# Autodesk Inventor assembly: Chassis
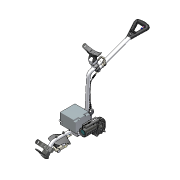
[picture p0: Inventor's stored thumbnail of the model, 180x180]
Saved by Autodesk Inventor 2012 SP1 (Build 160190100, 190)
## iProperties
Created: 2011-01
Part Number: Chassis
Document SubType Name: Assembly
Designer: eric
Mass: 5424.55 g
Surface Area: 15292.6 cm^2
Volume: 5424.55 cm^3
Density: 1 g/cm^3
Author: eric
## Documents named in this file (30)
- D:\Cours\Inventor salle SI\chariot_de_golf_2008\chariot_de_golf_trolem\Chassis.iam
- D:\Cours\Inventor salle SI\chariot_de_golf_2008\chariot_de_golf_trolem\59batterie_Defaut.ipt
- D:\Cours\Inventor salle SI\chariot_de_golf_2008\chariot_de_golf_trolem\montage1chassis_Defaut.iam
- D:\Cours\Inventor salle SI\chariot_de_golf_2008\chariot_de_golf_trolem\40Enjoliveur_M8_Defaut.ipt
- D:\Cours\Inventor salle SI\chariot_de_golf_2008\chariot_de_golf_trolem\5.1Vis CBLX M8-55.ipt
- D:\Cours\Inventor salle SI\chariot_de_golf_2008\chariot_de_golf_trolem\5.1cache-ecrouM10_Defaut.ipt
- D:\Cours\Inventor salle SI\chariot_de_golf_2008\chariot_de_golf_trolem\montage2timon_Defaut.iam
- D:\Cours\Inventor salle SI\chariot_de_golf_2008\chariot_de_golf_trolem\montage4tube_alu_Defaut.iam
- D:\Cours\Inventor salle SI\chariot_de_golf_2008\chariot_de_golf_trolem\montage_6cable_Defaut.iam
- D:\Cours\Inventor salle SI\chariot_de_golf_2008\chariot_de_golf_trolem\44Rondelle_M8_Defaut.ipt
- D:\Cours\Inventor salle SI\chariot_de_golf_2008\chariot_de_golf_trolem\33vis M6_60.ipt
- D:\Cours\Inventor salle SI\chariot_de_golf_2008\chariot_de_golf_trolem\32vis M8_60.ipt
- D:\Cours\Inventor salle SI\chariot_de_golf_2008\chariot_de_golf_trolem\39Ecrou H_ FR_ M8.ipt
- D:\Cours\Inventor salle SI\chariot_de_golf_2008\chariot_de_golf_trolem\35Vis_CBLZ_M6_55.ipt
- D:\Cours\Inventor salle SI\chariot_de_golf_2008\chariot_de_golf_trolem\36Ecrou H_ FR_ M6.ipt
- D:\Cours\Inventor salle SI\chariot_de_golf_2008\chariot_de_golf_trolem\30Ressort_e1.5_Defaut.ipt
- D:\Cours\Inventor salle SI\chariot_de_golf_2008\chariot_de_golf_trolem\5.1 ressort_Defaut.ipt
- D:\Cours\Inventor salle SI\chariot_de_golf_2008\chariot_de_golf_trolem\5.1Vis CBLX M8-45.ipt
- D:\Cours\Inventor salle SI\chariot_de_golf_2008\chariot_de_golf_trolem\39Ecrou H_FR_ M8.ipt
- D:\Cours\Inventor salle SI\chariot_de_golf_2008\chariot_de_golf_trolem\5.1rondelle plastique e8,5x2_Defaut.ipt
- D:\Cours\Inventor salle SI\chariot_de_golf_2008\chariot_de_golf_trolem\5.1carre_monte_Defaut.iam
- D:\Cours\Inventor salle SI\chariot_de_golf_2008\chariot_de_golf_trolem\70Rondelle_M10_Defaut.ipt
- D:\Cours\Inventor salle SI\chariot_de_golf_2008\chariot_de_golf_trolem\5.1Ecrou freine M 10.ipt
- D:\Cours\Inventor salle SI\chariot_de_golf_2008\chariot_de_golf_trolem\5.1Rondelle_e8_Defaut.ipt
- D:\Cours\Inventor salle SI\chariot_de_golf_2008\chariot_de_golf_trolem\68protection_roues_Defaut.ipt
- D:\Cours\Inventor salle SI\chariot_de_golf_2008\chariot_de_golf_trolem\38Rondelle plate_M8.ipt
- D:\Cours\Inventor salle SI\chariot_de_golf_2008\chariot_de_golf_trolem\69VisHM8_100_Defaut.ipt
- D:\Cours\Inventor salle SI\chariot_de_golf_2008\chariot_de_golf_trolem\12motoreducteur_Defaut.iam
- D:\Cours\Inventor salle SI\chariot_de_golf_2008\chariot_de_golf_trolem\5.1support_roue_monte_Defaut.iam
- D:\Cours\Inventor salle SI\chariot_de_golf_2008\chariot_de_golf_trolem\sac.ipt
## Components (49 placed, 29 different names)
1. 5.1support_roue_monte_Defaut:1 [sub-assembly]
2. 12motoreducteur_Defaut:1 [sub-assembly]
3. 35Vis_CBLZ_M6_55:2
4. 35Vis_CBLZ_M6_55:4
5. 35Vis_CBLZ_M6_55:3
6. 36Ecrou H_ FR_ M6:3
7. 36Ecrou H_ FR_ M6:4
8. 36Ecrou H_ FR_ M6:5
9. 36Ecrou H_ FR_ M6:2
10. 70Rondelle_M10_Defaut:3
11. 70Rondelle_M10_Defaut:4
12. 70Rondelle_M10_Defaut:5
13. 70Rondelle_M10_Defaut:2
14. 38Rondelle plate_M8:4
15. 38Rondelle plate_M8:5
16. 69VisHM8_100_Defaut:1
17. 38Rondelle plate_M8:1
18. 38Rondelle plate_M8:2
19. 38Rondelle plate_M8:3
20. 39Ecrou H_ FR_ M8:3
21. 68protection_roues_Defaut:1
22. 39Ecrou H_ FR_ M8:2
23. 5.1Rondelle_e8_Defaut:1
24. 5.1rondelle plastique e8,5x2_Defaut:3
25. 5.1Ecrou freine M 10:1
26. 70Rondelle_M10_Defaut:1
27. 5.1carre_monte_Defaut:1 [sub-assembly]
28. 5.1rondelle plastique e8,5x2_Defaut:1
29. 5.1rondelle plastique e8,5x2_Defaut:2
30. 39Ecrou H_FR_ M8:1
31. 5.1Vis CBLX M8-45:1
32. 5.1 ressort_Defaut:1
33. 35Vis_CBLZ_M6_55:1
34. 44Rondelle_M8_Defaut:2
35. 30Ressort_e1.5_Defaut:1
36. 33vis M6_60:1
37. 32vis M8_60:1
38. 44Rondelle_M8_Defaut:1
39. 39Ecrou H_ FR_ M8:1
40. 36Ecrou H_ FR_ M6:1
41. montage2timon_Defaut:1 [sub-assembly]
42. montage_6cable_Defaut:1 [sub-assembly]
43. montage4tube_alu_Defaut:1 [sub-assembly]
44. 5.1Vis CBLX M8-55:1
45. 5.1cache-ecrouM10_Defaut:1
46. 40Enjoliveur_M8_Defaut:1
47. montage1chassis_Defaut:1 [sub-assembly]
48. 59batterie_Defaut:1
49. sac:1
